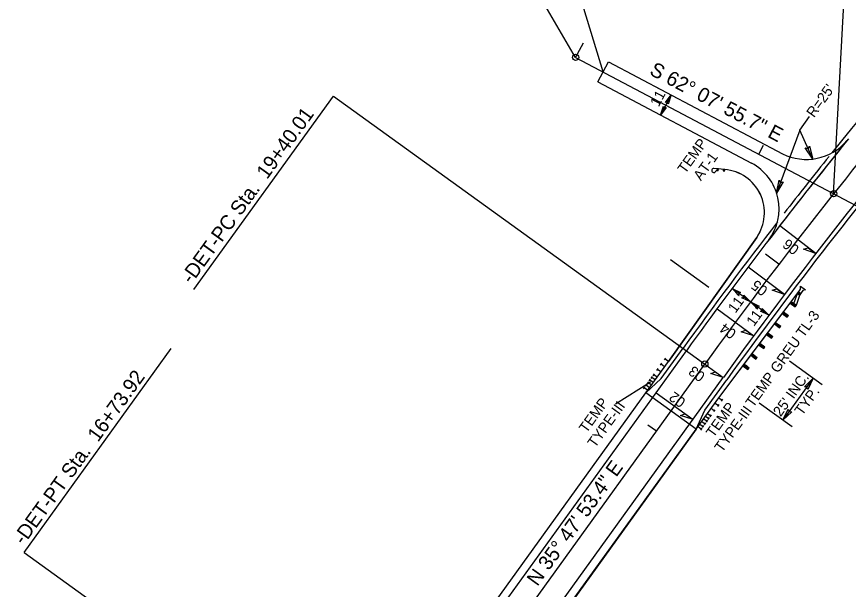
# Model space of a CAD drawing. Extents: x 2189637 to 2190858, y 386969 to 388736.
# Drawn here: x 2190060.2 to 2190461.8, y 387945.3 to 388222 of the extents above; entities that cross this region are included whole.
import ezdxf

# ---------------------------------------------------------------- set-up
doc = ezdxf.new("R2010")
doc.units = 0
for name, color, linetype in [('Exist Environmental Wetland Boundary Cogo Number', 7, 'Continuous'), ('Exist Environmental Wetland Boundary Cogo Point CELL', 7, 'Continuous'), ('Exist Horizontal Alignment Tick Label', 7, 'Continuous'), ('Exist Hydro Jurisdictional Stream or Body of Water Mitigable', 7, 'Continuous'), ('Exist Hydro Stream or Body of Water Leader', 7, 'Continuous'), ('Exist Hydro Swamp or Marsh', 7, 'Continuous'), ('Exist Property Corner CELL', 7, 'Continuous'), ('Exist Property Corner Cogo Elevation', 7, 'Continuous'), ('Exist Property Corner Cogo Number', 7, 'Continuous'), ('Exist Property Iron Pin Cogo Elevation', 7, 'Continuous'), ('Exist Property Iron Pin Cogo Number', 7, 'Continuous'), ('Exist Roads EOP', 7, 'Continuous'), ('Exist Roads EOT', 7, 'Continuous'), ('Exist Roads Soil', 7, 'Continuous'), ('Exist Structure Major Bridge Seam', 7, 'Continuous'), ('Exist Structure Minor Pipes RCP 18 Inch', 7, 'Continuous'), ('Exist Structure Minor Pipes RCP 18 Inch Cogo Comment', 7, 'Continuous'), ('Exist Structure Minor Pipes RCP 18 Inch Cogo Elevation', 7, 'Continuous'), ('Prop Parcel Number Text', 7, 'Continuous')]:
    doc.layers.add(name, color=color, linetype=linetype)

msp = doc.modelspace()

# ---------------------------------------------------------------- linework, layer by layer
at = {"layer": 'Exist Environmental Wetland Boundary Cogo Number'}
msp.add_line((2190402.07, 388148.14), (2190396.82, 388148.6), dxfattribs=at)
for points in [[(2190363.9, 388040.19), (2190374.87, 388055.4), (2190417.48, 388115.3)], [(2190388.25, 388022.63), (2190399.22, 388037.84), (2190437.44, 388088.68)]]:
    msp.add_lwpolyline(points, dxfattribs=at)
for centre, radius, start, end in [((2192257.95, 386708.79), 2311, 141.1011, 142.39738), ((2192257.95, 386708.79), 2313, 141.31622, 142.18227), ((2190400.25, 388127.25), 20.97, 325.2562, 85.0373)]:
    msp.add_arc(centre, radius, start, end, dxfattribs=at)
at = {"layer": 'Exist Environmental Wetland Boundary Cogo Point CELL'}
for p, q in [((2190330.06, 388202.3), (2190496.57, 388114.25)), ((2190236.81, 387838.31), (2190392.46, 388054.13))]:
    msp.add_line(p, q, dxfattribs=at)
msp.add_arc((2192257.95, 386708.79), 2300, 135.25499, 144.20184, dxfattribs=at)
at = {"layer": 'Exist Horizontal Alignment Tick Label'}
for p, q in [((2190418.46, 388155.55), (2190420.8, 388159.97)), ((2190369.06, 388021.68), (2190365, 388024.61))]:
    msp.add_line(p, q, dxfattribs=at)
at = {"layer": 'Exist Hydro Stream or Body of Water Leader'}
for p, q in [((2190330.06, 388202.3), (2190333.8, 388209.37)), ((2190428.18, 388102.33), (2190421.81, 388107.17))]:
    msp.add_line(p, q, dxfattribs=at)
at = {"layer": 'Exist Hydro Swamp or Marsh'}
for p, q in [((2190340.75, 388190.42), (2190345.89, 388200.15)), ((2190345.89, 388200.15), (2190429.97, 388155.69)), ((2190340.75, 388190.42), (2190414.99, 388151.17)), ((2190227.89, 387844.74), (2190383.54, 388060.57)), ((2190245.73, 387831.87), (2190401.38, 388047.7))]:
    msp.add_line(p, q, dxfattribs=at)
for centre, radius, start, end in [((2192257.95, 386708.79), 2289, 135.35973, 144.20184), ((2192257.95, 386708.79), 2311, 141.00543, 144.20184), ((2190441.43, 388178.87), 25.86, 243.6795, 319.487), ((2190403.31, 388129.07), 25, 322.549, 62.1383)]:
    msp.add_arc(centre, radius, start, end, dxfattribs=at)
at = {"layer": 'Exist Property Corner CELL'}
for p, q in [((2190371.38, 388047.13), (2190381.91, 388061.74)), ((2190363.91, 388040.19), (2190371.38, 388047.13)), ((2190392.47, 388031.92), (2190403, 388046.53)), ((2190262.13, 387899.06), (2190363.91, 388040.19)), ((2190388.24, 388022.64), (2190392.47, 388031.92)), ((2190388.24, 388022.64), (2190286.52, 387881.47))]:
    msp.add_line(p, q, dxfattribs=at)
for radius, start, end in [(2313, 135.25499, 141.26353), (2287, 135.97689, 144.20184), (2313, 142.31369, 144.20184)]:
    msp.add_arc((2192257.95, 386708.79), radius, start, end, dxfattribs=at)
at = {"layer": 'Exist Property Corner Cogo Elevation'}
for p, q in [((2190330.06, 388202.3), (2190276.32, 388294.58)), ((2190454.65, 388136.42), (2190461.68, 388265.94)), ((2190145.78, 388090.17), (2190213.08, 388183.49)), ((2190213.08, 388183.49), (2190391.24, 388055.01)), ((2190063.73, 387963.13), (2190134.8, 388061.68)), ((2190063.73, 387963.13), (2190235.59, 387839.18))]:
    msp.add_line(p, q, dxfattribs=at)
for centre in [(2190330.06, 388202.3), (2190454.65, 388136.42), (2190392.46, 388054.13)]:
    msp.add_circle(centre, 1.5, dxfattribs=at)
at = {"layer": 'Exist Property Corner Cogo Number'}
for p, q in [((2190262.13, 387899.06), (2190363.91, 388040.19)), ((2190388.24, 388022.64), (2190363.91, 388040.19)), ((2190286.46, 387881.51), (2190388.24, 388022.64))]:
    msp.add_line(p, q, dxfattribs=at)
at = {"layer": 'Exist Property Iron Pin Cogo Elevation'}
for p, q in [((2190446.02, 388107.52), (2190428.6, 388120.96)), ((2190430.92, 388087.74), (2190413.36, 388100.99)), ((2190398.34, 388080.86), (2190416.04, 388067.8)), ((2190383.54, 388060.57), (2190401.38, 388047.7)), ((2190368.91, 388040.29), (2190386.76, 388027.42))]:
    msp.add_line(p, q, dxfattribs=at)
for points in [[(2190446.02, 388107.52), (2190440.05, 388109.6), (2190442.36, 388110.34)], [(2190430.92, 388087.74), (2190424.93, 388089.76), (2190427.23, 388090.52)], [(2190416.04, 388067.8), (2190410.03, 388069.75), (2190412.32, 388070.54)], [(2190401.38, 388047.7), (2190395.34, 388049.59), (2190397.63, 388050.4)], [(2190386.76, 388027.42), (2190380.72, 388029.31), (2190383.01, 388030.13)]]:
    msp.add_lwpolyline(points, close=True, dxfattribs=at)
at = {"layer": 'Exist Property Iron Pin Cogo Number'}
msp.add_lwpolyline([(2190343.32, 388195.29), (2190318.28, 388277.7), (2190394.34, 388364.21)], dxfattribs=at)
at = {"layer": 'Exist Roads EOP'}
for p, q in [((2190376.18, 388184.14), (2190371.03, 388174.41)), ((2190438.35, 388167.15), (2190427.11, 388136.72)), ((2190449.18, 388044.05), (2190433.34, 388055.49)), ((2190444.77, 388047.24), (2190430.13, 388026.97)), ((2190434.56, 388023.77), (2190418.7, 388035.22))]:
    msp.add_line(p, q, dxfattribs=at)
msp.add_lwpolyline([(2190444.55, 388153.2), (2190438.35, 388167.15), (2190443, 388173.67)], dxfattribs=at)
at = {"layer": 'Exist Roads EOT'}
msp.add_line((2190423.39, 388077.7), (2190405.61, 388090.66), dxfattribs=at)
at = {"layer": 'Exist Roads Soil'}
for points in [[(2190373.39, 388180.52), (2190376.18, 388184.14), (2190374.77, 388179.76), (2190374.33, 388180.64)], [(2190373.82, 388178.03), (2190371.03, 388174.41), (2190372.44, 388178.79), (2190372.88, 388177.9)], [(2190442.98, 388159.4), (2190444.55, 388153.2), (2190440.95, 388158.53), (2190442.3, 388158.25)], [(2190430.34, 388142.23), (2190427.11, 388136.72), (2190428.29, 388143.04), (2190429.06, 388141.9)], [(2190408.78, 388087.37), (2190405.61, 388090.66), (2190409.73, 388088.63), (2190408.8, 388088.32)], [(2190411.31, 388087.45), (2190414.5, 388084.18), (2190410.37, 388086.19), (2190411.3, 388086.5)], [(2190417.67, 388080.9), (2190414.5, 388084.18), (2190418.62, 388082.15), (2190417.69, 388081.85)], [(2190420.21, 388080.98), (2190423.39, 388077.7), (2190419.26, 388079.72), (2190420.2, 388080.03)], [(2190440.53, 388043.09), (2190444.77, 388047.24), (2190442.17, 388041.86), (2190441.76, 388043.08)], [(2190434.38, 388031.13), (2190430.13, 388026.97), (2190432.74, 388032.35), (2190433.14, 388031.14)]]:
    msp.add_lwpolyline(points, close=True, dxfattribs=at)
at = {"layer": 'Exist Structure Major Bridge Seam'}
for p, q in [((2190398.54, 388148.46), (2190396.83, 388148.61)), ((2190397.48, 388146.97), (2190398.28, 388147.86)), ((2190398.34, 388148.48), (2190398.27, 388147.68)), ((2190399.04, 388148.42), (2190398.27, 388147.68)), ((2190398.27, 388147.68), (2190398.96, 388147.62)), ((2190398.34, 388148.48), (2190398.31, 388148.13)), ((2190398.34, 388148.48), (2190398.31, 388148.13)), ((2190399.04, 388148.42), (2190398.34, 388148.48)), ((2190398.34, 388148.48), (2190398.96, 388147.62)), ((2190398.47, 388148.47), (2190398.6, 388148.46)), ((2190398.47, 388148.47), (2190398.6, 388148.46)), ((2190402.07, 388148.15), (2190398.54, 388148.46)), ((2190398.96, 388147.62), (2190399.04, 388148.42)), ((2190401.37, 388148.21), (2190401.3, 388147.41)), ((2190402.07, 388148.15), (2190401.3, 388147.41)), ((2190401.3, 388147.41), (2190402, 388147.35)), ((2190402.07, 388148.15), (2190401.37, 388148.21)), ((2190401.37, 388148.21), (2190402, 388147.35)), ((2190402, 388147.35), (2190402.07, 388148.15)), ((2190437.52, 388088.66), (2190438.72, 388090.32)), ((2190437.74, 388089.08), (2190438.94, 388088.18)), ((2190437.74, 388089.08), (2190438.34, 388087.38)), ((2190439.71, 388089.6), (2190438.51, 388087.94)), ((2190438.72, 388090.32), (2190438.71, 388091.78)), ((2190438.71, 388091.78), (2190441.09, 388090.05)), ((2190441.09, 388090.05), (2190439.71, 388089.6)), ((2190409.34, 388051.32), (2190437.44, 388088.68)), ((2190435.42, 388083.44), (2190437.14, 388088.28)), ((2190436.64, 388082.52), (2190438.34, 388087.38)), ((2190437.14, 388088.28), (2190438.34, 388087.38)), ((2190438.94, 388088.18), (2190437.14, 388088.28)), ((2190438.01, 388088.3), (2190437.52, 388088.66)), ((2190438.51, 388087.94), (2190438.01, 388088.3)), ((2190438.34, 388087.38), (2190438.94, 388088.18)), ((2190438.34, 388087.38), (2190438.64, 388087.78)), ((2190433.59, 388083.57), (2190436.04, 388081.72)), ((2190433.59, 388083.57), (2190435.42, 388083.44)), ((2190434.19, 388084.37), (2190436.64, 388082.52)), ((2190434.81, 388082.65), (2190434.19, 388084.37)), ((2190434.81, 388082.65), (2190435.42, 388083.44)), ((2190436.64, 388082.52), (2190434.81, 388082.65)), ((2190435.42, 388083.44), (2190436.04, 388081.72)), ((2190436.04, 388081.72), (2190436.64, 388082.52)), ((2190429.8, 388078.53), (2190432.2, 388076.73)), ((2190429.8, 388078.53), (2190431.6, 388078.43)), ((2190430.4, 388079.33), (2190432.8, 388077.53)), ((2190431, 388077.63), (2190430.4, 388079.33)), ((2190431, 388077.63), (2190431.6, 388078.43)), ((2190432.8, 388077.53), (2190431, 388077.63)), ((2190431.6, 388078.43), (2190432.2, 388076.73)), ((2190432.2, 388076.73), (2190432.8, 388077.53)), ((2190426.01, 388073.49), (2190428.52, 388071.61)), ((2190426.01, 388073.49), (2190427.87, 388073.35)), ((2190426.62, 388074.29), (2190429.12, 388072.41)), ((2190427.27, 388072.55), (2190426.62, 388074.29)), ((2190427.27, 388072.55), (2190427.87, 388073.35)), ((2190427.87, 388073.35), (2190428.52, 388071.61)), ((2190422.23, 388068.46), (2190422.83, 388069.26)), ((2190422.83, 388069.26), (2190425.25, 388067.43)), ((2190423.44, 388067.55), (2190422.83, 388069.26)), ((2190429.12, 388072.41), (2190427.27, 388072.55)), ((2190428.52, 388071.61), (2190429.12, 388072.41)), ((2190422.23, 388068.46), (2190424.65, 388066.63)), ((2190422.23, 388068.46), (2190424.04, 388068.34)), ((2190423.44, 388067.55), (2190424.04, 388068.34)), ((2190425.25, 388067.43), (2190423.44, 388067.55)), ((2190424.04, 388068.34), (2190424.65, 388066.63)), ((2190424.65, 388066.63), (2190425.25, 388067.43)), ((2190418.44, 388063.42), (2190420.88, 388061.59)), ((2190418.44, 388063.42), (2190420.26, 388063.31)), ((2190419.04, 388064.22), (2190421.48, 388062.39)), ((2190419.66, 388062.51), (2190419.04, 388064.22)), ((2190419.66, 388062.51), (2190420.26, 388063.31)), ((2190421.48, 388062.39), (2190419.66, 388062.51)), ((2190420.26, 388063.31), (2190420.88, 388061.59)), ((2190420.88, 388061.59), (2190421.48, 388062.39)), ((2190414.65, 388058.39), (2190417.09, 388056.55)), ((2190414.65, 388058.39), (2190416.47, 388058.27)), ((2190415.25, 388059.18), (2190417.69, 388057.35)), ((2190415.87, 388057.47), (2190415.25, 388059.18)), ((2190415.87, 388057.47), (2190416.47, 388058.27)), ((2190417.69, 388057.35), (2190415.87, 388057.47)), ((2190416.47, 388058.27), (2190417.09, 388056.55)), ((2190417.09, 388056.55), (2190417.69, 388057.35)), ((2190410.87, 388053.35), (2190411.47, 388054.15)), ((2190410.87, 388053.35), (2190413.26, 388051.55)), ((2190412.67, 388053.25), (2190410.87, 388053.35)), ((2190411.47, 388054.15), (2190413.86, 388052.35)), ((2190411.47, 388054.15), (2190412.67, 388053.25)), ((2190412.06, 388052.45), (2190411.47, 388054.15)), ((2190412.06, 388052.45), (2190412.67, 388053.25)), ((2190412.67, 388053.25), (2190413.26, 388051.55)), ((2190413.86, 388052.35), (2190412.06, 388052.45)), ((2190413.26, 388051.55), (2190413.86, 388052.35)), ((2190366.18, 388045.34), (2190349.37, 388034.77))]:
    msp.add_line(p, q, dxfattribs=at)
msp.add_ellipse((2190396.74, 388147.63), major_axis=(-0.087, -0.989), ratio=0.995379, start_param=3.141593, end_param=7.214552, dxfattribs=at)
at = {"layer": 'Exist Structure Minor Pipes RCP 18 Inch'}
msp.add_arc((2190400.26, 388127.25), 20.98, 325.2463, 85.0472, dxfattribs=at)
at = {"layer": 'Exist Structure Minor Pipes RCP 18 Inch Cogo Comment'}
for p, q in [((2190417.49, 388115.29), (2190374.88, 388055.4)), ((2190399.21, 388037.85), (2190409.34, 388051.32))]:
    msp.add_line(p, q, dxfattribs=at)
at = {"layer": 'Exist Structure Minor Pipes RCP 18 Inch Cogo Elevation'}
for p, q in [((2190372.92, 388056.1), (2190373.59, 388057.03)), ((2190363.91, 388040.19), (2190374.88, 388055.4)), ((2190371.09, 388053.57), (2190371.76, 388054.5)), ((2190373.05, 388052.86), (2190371.43, 388054.03)), ((2190374.88, 388055.4), (2190373.25, 388056.57)), ((2190367.43, 388048.5), (2190368.1, 388049.43)), ((2190369.39, 388047.79), (2190367.77, 388048.96)), ((2190369.26, 388051.03), (2190369.93, 388051.96)), ((2190371.22, 388050.33), (2190369.6, 388051.5)), ((2190364.69, 388044.69), (2190365.36, 388045.62)), ((2190366.65, 388043.99), (2190365.03, 388045.16)), ((2190365.61, 388045.96), (2190366.28, 388046.89)), ((2190367.56, 388045.26), (2190365.94, 388046.43)), ((2190366.52, 388047.23), (2190367.19, 388048.16)), ((2190368.48, 388046.52), (2190366.86, 388047.69)), ((2190362.86, 388042.16), (2190363.53, 388043.09)), ((2190364.82, 388041.46), (2190363.2, 388042.62)), ((2190363.78, 388043.43), (2190364.45, 388044.36)), ((2190365.74, 388042.72), (2190364.11, 388043.89)), ((2190388.24, 388022.64), (2190399.21, 388037.85)), ((2190399.21, 388037.85), (2190400.83, 388036.68)), ((2190400.5, 388036.21), (2190401.17, 388037.14)), ((2190395.55, 388032.78), (2190397.17, 388031.61)), ((2190397.38, 388035.31), (2190399, 388034.14)), ((2190398.67, 388033.68), (2190399.34, 388034.61)), ((2190392.81, 388028.98), (2190394.43, 388027.81)), ((2190393.72, 388030.24), (2190395.35, 388029.07)), ((2190395.01, 388028.61), (2190395.68, 388029.54)), ((2190396.84, 388031.14), (2190397.51, 388032.07)), ((2190390.07, 388025.17), (2190391.69, 388024)), ((2190390.98, 388026.44), (2190392.6, 388025.27)), ((2190391.9, 388027.71), (2190393.52, 388026.54)), ((2190392.27, 388024.81), (2190392.94, 388025.74)), ((2190393.18, 388026.07), (2190393.85, 388027)), ((2190394.1, 388027.34), (2190394.77, 388028.27)), ((2190389.15, 388023.91), (2190390.78, 388022.74)), ((2190390.44, 388022.27), (2190391.11, 388023.2)), ((2190391.36, 388023.54), (2190392.03, 388024.47))]:
    msp.add_line(p, q, dxfattribs=at)
at = {"layer": 'Prop Parcel Number Text'}
msp.add_line((2190394.45, 388091.08), (2190375.94, 388104.43), dxfattribs=at)

# ---------------------------------------------------------------- texts
at = {"layer": 'Exist Hydro Jurisdictional Stream or Body of Water Mitigable'}
for s, rotation, p in [('S 62%%d 07\' 55.7" E', 332.1321, (2190365.25, 388194.24)), ('N 35%%d 47\' 53.4" E', 54.2018, (2190311.6, 387946.42))]:
    msp.add_text(s, height=7, rotation=rotation, dxfattribs=at).set_placement(p)
at = {"layer": 'Exist Property Corner Cogo Elevation'}
for s, p in [('-DET-PC Sta.  19+40.01', (2190144.57, 388092.43)), ('-DET-PT Sta.  16+73.92', (2190063.56, 387966.32))]:
    msp.add_text(s, height=7, rotation=54.2018, dxfattribs=at).set_placement(p)
at = {"layer": 'Exist Roads EOT'}
for s, rotation, p in [("R=25'", 54.2018, (2190445.14, 388172.88)), ("11'", 62.1321, (2190370.15, 388178.09)), ("11'", 54.2018, (2190407.24, 388078.41)), ("11'", 54.2018, (2190416.13, 388072.01)), ("25' INC.", 54.2018, (2190429.05, 388028.4)), ('TYP.', 54.2018, (2190439.44, 388028.92))]:
    msp.add_text(s, height=5, rotation=rotation, dxfattribs=at).set_placement(p)
at = {"layer": 'Exist Structure Major Bridge Seam'}
for s, p in [('TEMP', (2190382.96, 388145.74)), ('AT-1', (2190390.55, 388142.38)), ('TEMP GREU TL-3', (2190415.78, 388032.81)), ('TEMP', (2190335.35, 388020.46)), ('TYPE-III', (2190339.47, 388013.36)), ('TEMP', (2190396.65, 388018.25)), ('TYPE-III', (2190400.77, 388011.14))]:
    msp.add_text(s, height=5, rotation=54.2018, dxfattribs=at).set_placement(p)
at = {"layer": 'Prop Parcel Number Text'}
for s, rotation, p in [('06', 142.3587, (2190438.43, 388110.43)), ('05', 142.9815, (2190423.24, 388090.62)), ('04', 144.227, (2190408.03, 388069.89)), ('03', 144.227, (2190392.98, 388049.21)), ('02', 144.227, (2190383.58, 388036.76))]:
    msp.add_text(s, height=5, rotation=rotation, dxfattribs=at).set_placement(p)

doc.saveas('drawing.dxf')
